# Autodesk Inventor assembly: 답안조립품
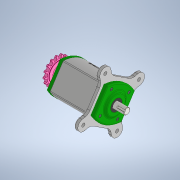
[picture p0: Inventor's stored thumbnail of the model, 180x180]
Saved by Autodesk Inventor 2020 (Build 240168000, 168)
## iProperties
Created: 2022-01
Part Number: 답안조립품
Document SubType Name: Assembly
Designer: user
Author: user
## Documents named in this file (13)
- C:\Users\user\Desktop\720117V1010\답안조립품.iam
- C:\Users\user\Desktop\720117V1010\베어링 6203.ipt
- C:\Users\user\Desktop\720117V1010\본체.ipt
- C:\Users\user\Desktop\720117V1010\볼트 M4 x 12.ipt
- C:\Users\user\Desktop\720117V1010\부시.ipt
- C:\Users\user\Desktop\720117V1010\스프로킷.ipt
- C:\Users\user\Desktop\720117V1010\슬라이더.ipt
- C:\Users\user\Desktop\720117V1010\오일 실 17 x 30 x 8.ipt
- C:\Users\user\Desktop\720117V1010\와셔 4 x 20.ipt
- C:\Users\user\Desktop\720117V1010\육각머리볼트 M4.ipt
- C:\Users\user\Desktop\720117V1010\커버.ipt
- C:\Users\user\Desktop\720117V1010\키 5 x 5.ipt
- C:\Users\user\Desktop\720117V1010\편심축.ipt
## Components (8 placed, 1 different names)
1. M4x0.7x12:1
2. M4x0.7x12:3
3. M4x0.7x12:4
4. M4x0.7x12:5
5. M4x0.7x12:2
6. M4x0.7x12:6
7. M4x0.7x12:7
8. M4x0.7x12:8
